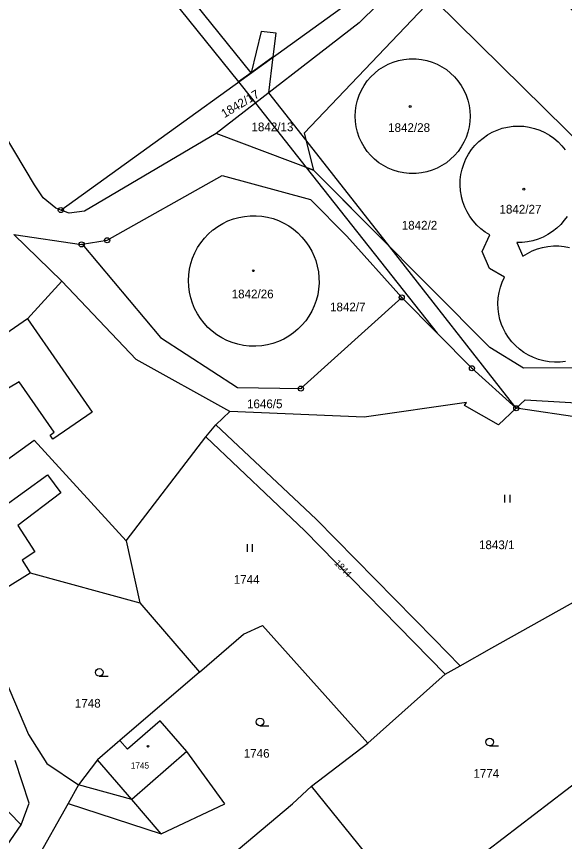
# Model space of a CAD drawing. Extents: x -504988 to -494607, y -1123820 to -1114018.
# Drawn here: x -497897.9 to -497790.5, y -1119099.6 to -1118938 of the extents above; entities that cross this region are included whole.
import ezdxf

# ---------------------------------------------------------------- set-up
doc = ezdxf.new("R2010")
doc.units = 0
for name, color, linetype in [('Hranice parcel', 7, 'Continuous'), ('Parcelní čísla', 7, 'Continuous'), ('Vnitřní kresba', 7, 'Continuous'), ('Věcná břemena k části', 7, 'Continuous'), ('Značky bodu BP', 7, 'Continuous'), ('Značky budov', 7, 'Continuous'), ('Značky kultur', 7, 'Continuous')]:
    doc.layers.add(name, color=color, linetype=linetype)

msp = doc.modelspace()

# ---------------------------------------------------------------- linework, layer by layer
at = {"layer": 'Hranice parcel'}
for p, q in [((-497889.18, -1118975.93), (-497826.74, -1118930.91)), ((-497839.68, -1118968.12), (-497858.74, -1118960.94)), ((-497898.41, -1118980.72), (-497888.97, -1118989.83)), ((-497833.18, -1118981.07), (-497822.4, -1118993.03)), ((-497884.99, -1118982.64), (-497880.12, -1118981.85)), ((-497884.99, -1118982.64), (-497869.68, -1119000.91)), ((-497799.87, -1118982.29), (-497798.67, -1118984.98)), ((-497869.68, -1119000.91), (-497854.59, -1119010.65)), ((-497771.22, -1119019.03), (-497799.96, -1119014.75)), ((-497858.82, -1119017.97), (-497856.09, -1119015.39)), ((-497860.76, -1119020.36), (-497858.82, -1119017.97)), ((-497876.41, -1119040.69), (-497860.76, -1119020.36)), ((-497876.41, -1119040.69), (-497873.68, -1119052.85)), ((-497873.68, -1119052.85), (-497862.05, -1119066.42)), ((-497813.91, -1119066.81), (-497810.95, -1119065.16)), ((-497862.05, -1119066.42), (-497877.65, -1119079.79)), ((-497829.06, -1119080.32), (-497813.91, -1119066.81)), ((-497840.07, -1119088.75), (-497829.06, -1119080.32)), ((-497896.94, -1119096.33), (-497904.11, -1119089.02)), ((-497885.74, -1119088.5), (-497887.77, -1119092.18)), ((-497826.23, -1119105.84), (-497840.07, -1119088.75)), ((-497887.77, -1119092.18), (-497896.72, -1119107.97))]:
    msp.add_line(p, q, dxfattribs=at)
for points in [[(-497783.55, -1118899.96), (-497841.51, -1118960.88), (-497839.68, -1118968.12)], [(-497803.78, -1118922.28), (-497815.78, -1118935.05), (-497764.51, -1118985.45), (-497752.56, -1118972.3), (-497803.78, -1118922.28)], [(-497889.18, -1118975.93), (-497890.14, -1118975.57), (-497892.62, -1118973.53), (-497894.35, -1118971.02), (-497916.29, -1118934.26), (-497922.49, -1118923.59)], [(-497826.74, -1118930.91), (-497825.68, -1118932.98), (-497827.1, -1118935.66), (-497830.72, -1118939.27), (-497858.74, -1118960.94)], [(-497831.52, -1118957.54), (-497831.47, -1118956.48), (-497831.32, -1118955.43), (-497831.07, -1118954.4), (-497830.73, -1118953.4), (-497830.29, -1118952.43), (-497829.76, -1118951.51), (-497829.15, -1118950.64), (-497828.46, -1118949.83), (-497827.7, -1118949.1), (-497826.87, -1118948.43), (-497825.98, -1118947.85), (-497825.05, -1118947.36), (-497824.07, -1118946.95), (-497823.05, -1118946.64), (-497822.01, -1118946.43), (-497820.96, -1118946.31), (-497820.63, -1118946.3), (-497819.57, -1118946.31), (-497818.52, -1118946.43), (-497817.48, -1118946.64), (-497816.46, -1118946.95), (-497815.48, -1118947.36), (-497814.54, -1118947.85), (-497813.66, -1118948.43), (-497812.83, -1118949.1), (-497812.07, -1118949.83), (-497811.38, -1118950.64), (-497810.77, -1118951.51), (-497810.24, -1118952.43), (-497809.8, -1118953.4), (-497809.46, -1118954.4), (-497809.21, -1118955.43), (-497809.06, -1118956.48), (-497809.01, -1118957.54), (-497809.06, -1118958.6), (-497809.21, -1118959.65), (-497809.46, -1118960.68), (-497809.8, -1118961.69), (-497810.24, -1118962.65), (-497810.76, -1118963.57), (-497811.37, -1118964.44), (-497812.06, -1118965.25), (-497812.82, -1118965.99), (-497813.65, -1118966.65), (-497814.54, -1118967.23), (-497815.47, -1118967.73), (-497816.45, -1118968.14), (-497817.47, -1118968.45), (-497818.51, -1118968.66), (-497819.56, -1118968.78), (-497819.91, -1118968.79), (-497820.97, -1118968.78), (-497822.02, -1118968.66), (-497823.06, -1118968.45), (-497824.08, -1118968.14), (-497825.06, -1118967.73), (-497825.99, -1118967.23), (-497826.88, -1118966.65), (-497827.71, -1118965.99), (-497828.47, -1118965.25), (-497829.16, -1118964.44), (-497829.77, -1118963.57), (-497830.29, -1118962.65), (-497830.73, -1118961.69), (-497831.07, -1118960.68), (-497831.32, -1118959.65), (-497831.47, -1118958.6), (-497831.52, -1118957.54)], [(-497805.14, -1118980.79), (-497806.04, -1118980.23), (-497806.89, -1118979.58), (-497807.68, -1118978.86), (-497808.39, -1118978.07), (-497809.03, -1118977.21), (-497809.58, -1118976.3), (-497810.04, -1118975.34), (-497810.42, -1118974.34), (-497810.7, -1118973.31), (-497810.72, -1118973.2), (-497810.89, -1118972.15), (-497810.96, -1118971.08), (-497810.93, -1118970.02), (-497810.8, -1118968.96), (-497810.57, -1118967.92), (-497810.25, -1118966.91), (-497809.83, -1118965.92), (-497809.32, -1118964.99), (-497808.72, -1118964.1), (-497808.05, -1118963.28), (-497807.3, -1118962.52), (-497806.48, -1118961.83), (-497805.61, -1118961.22), (-497804.68, -1118960.7), (-497803.71, -1118960.26), (-497802.7, -1118959.92), (-497801.66, -1118959.68), (-497800.6, -1118959.53), (-497799.54, -1118959.48), (-497798.47, -1118959.53), (-497797.41, -1118959.69), (-497796.37, -1118959.94), (-497795.36, -1118960.28), (-497794.39, -1118960.73), (-497793.46, -1118961.25), (-497792.59, -1118961.87), (-497791.78, -1118962.56), (-497791.04, -1118963.32), (-497790.37, -1118964.16)], [(-497858.74, -1118960.94), (-497884.52, -1118976.12), (-497887.58, -1118976.54), (-497889.18, -1118975.93)], [(-497784.97, -1119006.83), (-497798.54, -1119006.88), (-497805.13, -1119002.84), (-497839.68, -1118968.12)], [(-497880.12, -1118981.85), (-497857.57, -1118969.18), (-497840.26, -1118973.89), (-497833.18, -1118981.07)], [(-497843.62, -1118979.69), (-497842.75, -1118980.42), (-497841.95, -1118981.22), (-497841.23, -1118982.09), (-497840.58, -1118983.02), (-497840.02, -1118984), (-497839.54, -1118985.03), (-497839.25, -1118985.81), (-497838.94, -1118986.9), (-497838.73, -1118988.01), (-497838.61, -1118989.14), (-497838.6, -1118990.27), (-497838.68, -1118991.4), (-497838.87, -1118992.52), (-497839.15, -1118993.61), (-497839.53, -1118994.68), (-497840.01, -1118995.71), (-497840.57, -1118996.69), (-497841.22, -1118997.61), (-497841.95, -1118998.48), (-497842.75, -1118999.28), (-497843.62, -1119000), (-497844.55, -1119000.65), (-497845.53, -1119001.21), (-497846.56, -1119001.68), (-497847.63, -1119002.05), (-497848.72, -1119002.34), (-497849.84, -1119002.52), (-497850.97, -1119002.61), (-497851.17, -1119002.61), (-497852.3, -1119002.58), (-497853.43, -1119002.45), (-497854.53, -1119002.21), (-497855.62, -1119001.89), (-497856.67, -1119001.46), (-497857.67, -1119000.95), (-497858.63, -1119000.35), (-497859.54, -1118999.67), (-497860.37, -1118998.91), (-497861.14, -1118998.08), (-497861.83, -1118997.18), (-497862.44, -1118996.23), (-497862.97, -1118995.23), (-497863.4, -1118994.18), (-497863.74, -1118993.1), (-497863.98, -1118992), (-497864.13, -1118990.88), (-497864.18, -1118989.75), (-497864.12, -1118988.62), (-497863.97, -1118987.5), (-497863.72, -1118986.4), (-497863.37, -1118985.33), (-497862.92, -1118984.29), (-497862.39, -1118983.29), (-497861.77, -1118982.35), (-497861.07, -1118981.46), (-497860.3, -1118980.64), (-497859.45, -1118979.89), (-497859.35, -1118979.8), (-497858.44, -1118979.14), (-497857.47, -1118978.56), (-497856.45, -1118978.07), (-497855.39, -1118977.67), (-497854.31, -1118977.37), (-497853.2, -1118977.16), (-497852.07, -1118977.05), (-497850.94, -1118977.04), (-497849.82, -1118977.14), (-497848.7, -1118977.33), (-497847.61, -1118977.61), (-497846.55, -1118978), (-497845.52, -1118978.48), (-497844.54, -1118979.04), (-497843.62, -1118979.69)], [(-497790.02, -1118977.18), (-497790.57, -1118977.94), (-497791.26, -1118978.75), (-497792.03, -1118979.49), (-497792.86, -1118980.15), (-497793.76, -1118980.73), (-497794.7, -1118981.23), (-497795.68, -1118981.63), (-497796.7, -1118981.95), (-497797.75, -1118982.16), (-497798.8, -1118982.28), (-497799.87, -1118982.29)], [(-497898.41, -1118980.72), (-497885.11, -1118982.66), (-497884.99, -1118982.64)], [(-497802.27, -1118989.1), (-497805.22, -1118987.35), (-497806.63, -1118984.06), (-497805.14, -1118980.79)], [(-497798.67, -1118984.98), (-497797.77, -1118984.41), (-497796.82, -1118983.93), (-497795.83, -1118983.55), (-497794.8, -1118983.25), (-497793.76, -1118983.06), (-497792.7, -1118982.96), (-497791.63, -1118982.96), (-497790.57, -1118983.07), (-497789.53, -1118983.27)], [(-497790.33, -1119005.57), (-497791.39, -1119005.69), (-497792.45, -1119005.71), (-497793.51, -1119005.64), (-497794.56, -1119005.46), (-497795.59, -1119005.18), (-497796.58, -1119004.81), (-497797.54, -1119004.35), (-497798.46, -1119003.81), (-497799.32, -1119003.19), (-497800.11, -1119002.48), (-497800.84, -1119001.71), (-497801.5, -1119000.87), (-497802.07, -1118999.97), (-497802.55, -1118999.03), (-497802.83, -1118998.37), (-497803.16, -1118997.36), (-497803.39, -1118996.32), (-497803.53, -1118995.27), (-497803.56, -1118994.21), (-497803.5, -1118993.15), (-497803.34, -1118992.1), (-497803.08, -1118991.06), (-497802.72, -1118990.06), (-497802.27, -1118989.1)], [(-497888.97, -1118989.83), (-497895.69, -1118997.23), (-497905.35, -1119003.8), (-497907.1, -1119001.27), (-497923.6, -1119012.04), (-497926.21, -1119008.04), (-497931.27, -1119011.29), (-497928.61, -1119015.31), (-497934.89, -1119019.41), (-497929.22, -1119028.07), (-497926.61, -1119032.05)], [(-497856.09, -1119015.39), (-497874.43, -1119005.2), (-497888.97, -1118989.83)], [(-497854.59, -1119010.65), (-497842.15, -1119010.89), (-497822.4, -1118993.03)], [(-497822.4, -1118993.03), (-497808.65, -1119006.92), (-497799.96, -1119014.75)], [(-497799.96, -1119014.75), (-497798.19, -1119013.11), (-497772.47, -1119014.6), (-497761, -1119024.56)], [(-497809.7, -1119013.6), (-497829.77, -1119016.47), (-497856.09, -1119015.39)], [(-497799.96, -1119014.75), (-497803.42, -1119017.97), (-497810.09, -1119014.2), (-497809.7, -1119013.6)], [(-497858.82, -1119017.97), (-497839.18, -1119036.45), (-497816.07, -1119059.94), (-497810.95, -1119065.16)], [(-497909.4, -1119035.01), (-497910.99, -1119032.96), (-497894.43, -1119020.98), (-497876.41, -1119040.69)], [(-497813.91, -1119066.81), (-497841.38, -1119038.78), (-497860.76, -1119020.36)], [(-497906.66, -1119038.58), (-497899.68, -1119049.76), (-497895.2, -1119046.97), (-497873.68, -1119052.85)], [(-497906.66, -1119038.58), (-497906.06, -1119046.33), (-497903.84, -1119059.25), (-497895.52, -1119078.66), (-497891.9, -1119084.3), (-497885.74, -1119088.5)], [(-497810.95, -1119065.16), (-497804.73, -1119061.68), (-497783.83, -1119049.98)], [(-497862.05, -1119066.42), (-497853.39, -1119059), (-497849.69, -1119057.28), (-497829.06, -1119080.32)], [(-497768.75, -1119073.13), (-497820.97, -1119113.09), (-497826.23, -1119105.84)], [(-497887.77, -1119092.18), (-497869.56, -1119098.12), (-497857.03, -1119092.22), (-497864.5, -1119081.98), (-497869.74, -1119075.96), (-497876.13, -1119081.53), (-497877.65, -1119079.79)], [(-497877.65, -1119079.79), (-497882.03, -1119083.6), (-497885.74, -1119088.5)], [(-497896.94, -1119096.33), (-497895.42, -1119092.08), (-497898.12, -1119083.72)], [(-497872.49, -1119116.3), (-497843.78, -1119092.19), (-497840.07, -1119088.75)], [(-497913.33, -1119120.02), (-497906.12, -1119109.53), (-497896.94, -1119096.33)]]:
    msp.add_lwpolyline(points, dxfattribs=at)
at = {"layer": 'Vnitřní kresba'}
for p, q in [((-497895.69, -1118997.23), (-497883.04, -1119015.49)), ((-497897.32, -1119009.56), (-497929.22, -1119028.07)), ((-497890.48, -1119019.43), (-497897.32, -1119009.56)), ((-497883.04, -1119015.49), (-497890.73, -1119020.82)), ((-497891.3, -1119020), (-497890.48, -1119019.43)), ((-497890.73, -1119020.82), (-497891.3, -1119020)), ((-497900.78, -1119034.3), (-497891.81, -1119027.76)), ((-497891.81, -1119027.76), (-497889.19, -1119031.3)), ((-497889.19, -1119031.3), (-497897.63, -1119037.73)), ((-497897.63, -1119037.73), (-497894.29, -1119042.89)), ((-497894.29, -1119042.89), (-497896.74, -1119044.48)), ((-497896.74, -1119044.48), (-497895.2, -1119046.97)), ((-497864.5, -1119081.98), (-497875.26, -1119091.37)), ((-497875.26, -1119091.37), (-497882.03, -1119083.6)), ((-497875.26, -1119091.37), (-497885.74, -1119088.5)), ((-497869.56, -1119098.12), (-497875.26, -1119091.37))]:
    msp.add_line(p, q, dxfattribs=at)
at = {"layer": 'Věcná břemena k části'}
for points in [[(-497893.32, -1118902.49), (-497854.38, -1118950.84), (-497851.91, -1118949.05), (-497890.86, -1118900.71)], [(-497851.91, -1118949.05), (-497847.56, -1118945.92), (-497846.99, -1118941.27), (-497849.97, -1118940.93)], [(-497847.56, -1118945.92), (-497851.91, -1118949.05), (-497854.38, -1118950.84), (-497851.82, -1118954.01), (-497851.05, -1118954.99), (-497841.1, -1118967.59), (-497839.68, -1118968.12), (-497824.71, -1118983.16), (-497841.19, -1118962.16), (-497848.41, -1118952.95)], [(-497841.1, -1118967.59), (-497815.49, -1119000.01), (-497808.65, -1119006.92), (-497799.96, -1119014.75), (-497824.71, -1118983.16), (-497839.68, -1118968.12)]]:
    msp.add_lwpolyline(points, close=True, dxfattribs=at)
at = {"layer": 'Značky bodu BP'}
for centre, radius in [((-497889.18, -1118975.93), 0.5), ((-497889.18, -1118975.93), 0.0303), ((-497885.11, -1118982.66), 0.5), ((-497885.11, -1118982.66), 0.0303), ((-497880.12, -1118981.85), 0.5), ((-497880.12, -1118981.85), 0.0303), ((-497822.4, -1118993.03), 0.5), ((-497822.4, -1118993.03), 0.0303), ((-497808.65, -1119006.92), 0.5), ((-497808.65, -1119006.92), 0.0303), ((-497842.15, -1119010.89), 0.5), ((-497842.15, -1119010.89), 0.0303), ((-497799.96, -1119014.75), 0.5), ((-497799.96, -1119014.75), 0.0303)]:
    msp.add_circle(centre, radius, dxfattribs=at)
at = {"layer": 'Značky budov'}
for centre in [(-497820.75, -1118955.64), (-497798.47, -1118971.83), (-497851.48, -1118987.82), (-497872.11, -1119080.95)]:
    msp.add_circle(centre, 0.175, dxfattribs=at)
at = {"layer": 'Značky kultur'}
for p, q in [((-497802.19, -1119033.2), (-497802.19, -1119031.7)), ((-497801.19, -1119033.2), (-497801.19, -1119031.7)), ((-497852.65, -1119042.88), (-497852.65, -1119041.38)), ((-497851.65, -1119042.88), (-497851.65, -1119041.38)), ((-497881.67, -1119067.24), (-497879.92, -1119067.24)), ((-497850.17, -1119076.93), (-497848.42, -1119076.93)), ((-497805.18, -1119080.87), (-497803.43, -1119080.87))]:
    msp.add_line(p, q, dxfattribs=at)
for centre in [(-497881.67, -1119066.49), (-497850.17, -1119076.18), (-497805.18, -1119080.12)]:
    msp.add_circle(centre, 0.75, dxfattribs=at)

# ---------------------------------------------------------------- texts
at = {"layer": 'Parcelní čísla'}
for s, height, rotation, p in [('1842/17', 1.7, 31, (-497857.14, -1118957.95)), ('1844', 1.3, 314, (-497835.7, -1119045.18))]:
    msp.add_text(s, height=height, rotation=rotation, dxfattribs=at).set_placement(p)
for s, height, p in [('1842/13', 1.7, (-497851.84, -1118960.49)), ('1842/28', 1.7, (-497825.07, -1118960.63)), ('1842/27', 1.7, (-497803.25, -1118976.61)), ('1842/2', 1.7, (-497822.4, -1118979.75)), ('1842/26', 1.7, (-497855.72, -1118993.21)), ('1842/7', 1.7, (-497836.45, -1118995.76)), ('1646/5', 1.7, (-497852.72, -1119014.73)), ('1843/1', 1.7, (-497807.27, -1119042.34)), ('1744', 1.7, (-497855.31, -1119049.13)), ('1748', 1.7, (-497886.44, -1119073.37)), ('1746', 1.7, (-497853.35, -1119083.18)), ('1745', 1.2, (-497875.47, -1119085.31)), ('1774', 1.7, (-497808.36, -1119087.12))]:
    msp.add_text(s, height=height, dxfattribs=at).set_placement(p)

doc.saveas('drawing.dxf')
